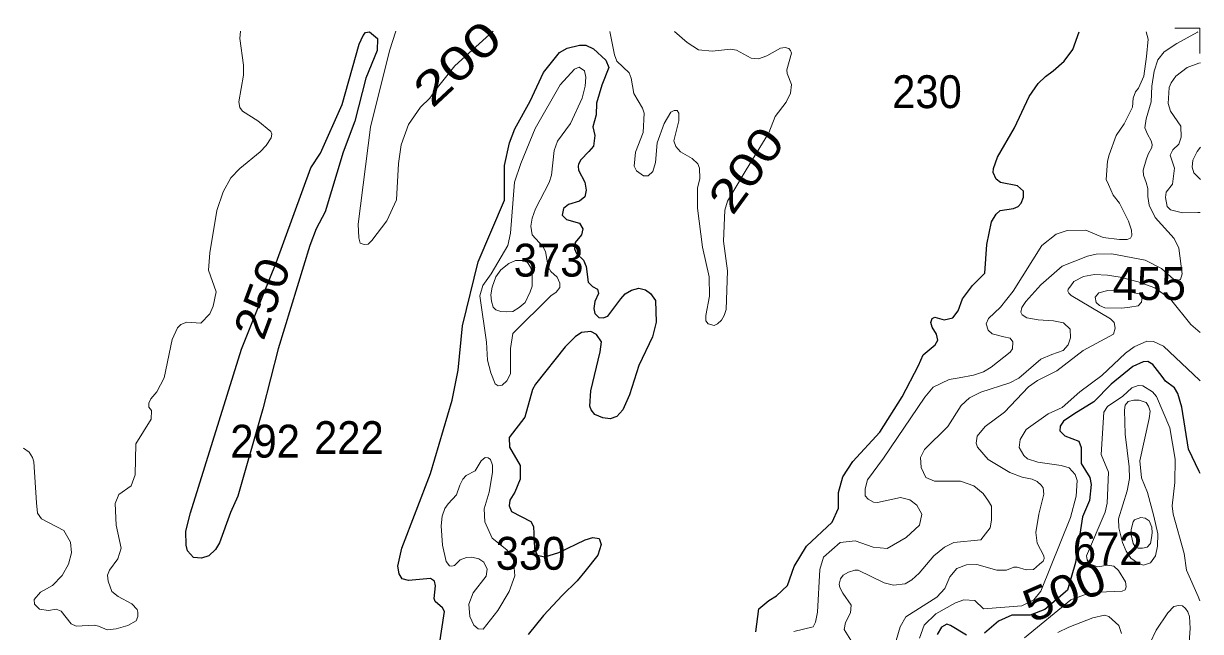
# Model space of a CAD drawing. Extents: x 499.9 to 555.3, y 9281.5 to 9336.8.
# Drawn here: x 549.61 to 555.34, y 9333.84 to 9336.8 of the extents above; entities that cross this region are included whole.
import ezdxf
from ezdxf.enums import TextEntityAlignment as Align

# ---------------------------------------------------------------- set-up
doc = ezdxf.new("R2010")
doc.units = 0
doc.header["$LTSCALE"] = 0.064
for name, color, linetype, lineweight in [('1', 7, 'Continuous', 25), ('2', 7, 'Continuous', 13), ('63', 7, 'Continuous', 13)]:
    doc.layers.add(name, color=color, linetype=linetype, lineweight=lineweight)
doc.layers.add('21', color=7, linetype='Continuous')
doc.layers.add('61', color=7, linetype='Continuous')

msp = doc.modelspace()

# ---------------------------------------------------------------- linework, layer by layer
at = {"layer": '1'}
msp.add_lwpolyline([(550.4187, 9334.4223), (550.6665, 9335.2176), (550.7746, 9335.4868), (550.8353, 9335.6382), (551.0048, 9336.1013), (551.0522, 9336.1729), (551.1571, 9336.4093), (551.2399, 9336.7025), (551.2589, 9336.7457), (551.2711, 9336.7591), (551.2901, 9336.7636), (551.3297, 9336.7309), (551.3282, 9336.6715), (551.2731, 9336.5372), (551.2185, 9336.3289), (551.1616, 9336.1779), (551.0748, 9335.8875), (551.0312, 9335.8041), (550.9998, 9335.7224), (550.8455, 9335.2205), (550.7715, 9334.928), (550.649, 9334.5029), (550.6129, 9334.4235), (550.5599, 9334.2763), (550.5396, 9334.2439), (550.5082, 9334.2127), (550.4722, 9334.2007), (550.433, 9334.2051), (550.4041, 9334.2372), (550.3978, 9334.2644), (550.3962, 9334.3327)], close=True, dxfattribs=at)
for points in [[(553.1716, 9333.8418), (553.1865, 9333.9546), (553.2346, 9333.9949), (553.2721, 9334.017), (553.3255, 9334.0688), (553.3578, 9334.1608), (553.4181, 9334.2595), (553.5429, 9334.3758), (553.5742, 9334.445), (553.5746, 9334.5213), (553.5964, 9334.5966), (553.6446, 9334.6709), (553.7755, 9334.8149), (553.8848, 9334.9861), (553.9645, 9335.1389), (553.9876, 9335.1907), (554.0164, 9335.2146), (554.045, 9335.2397), (554.0581, 9335.2624), (554.0513, 9335.2909), (554.0301, 9335.3252), (554.0246, 9335.3485), (554.0304, 9335.3675), (554.0438, 9335.3748), (554.0892, 9335.3604), (554.1319, 9335.3705), (554.1569, 9335.4047), (554.1778, 9335.4635), (554.2271, 9335.5288), (554.2871, 9335.5879), (554.2972, 9335.7286), (554.3192, 9335.8383), (554.3419, 9335.8757), (554.3617, 9335.8933), (554.4272, 9335.9024), (554.4496, 9335.9128), (554.4646, 9335.9291), (554.4753, 9335.9586), (554.4749, 9335.9869), (554.4463, 9336.013), (554.3642, 9336.0289), (554.3419, 9336.0453), (554.3282, 9336.0777), (554.3287, 9336.0973), (554.3493, 9336.1535), (554.4316, 9336.2964), (554.5028, 9336.4478), (554.5462, 9336.5116), (554.5821, 9336.5458), (554.6194, 9336.5723), (554.6731, 9336.6198), (554.716, 9336.6772), (554.7464, 9336.7634)], [(551.6297, 9333.771), (551.6563, 9333.9413), (551.6461, 9333.9597), (551.6103, 9333.9906), (551.6045, 9334.0042), (551.6119, 9334.0662), (551.607, 9334.0898), (551.5866, 9334.1027), (551.4809, 9334.0919), (551.4494, 9334.1004), (551.4346, 9334.1248), (551.428, 9334.1623), (551.4473, 9334.2497), (551.5866, 9334.6137), (551.693, 9334.9694), (551.7218, 9335.1158), (551.744, 9335.3322), (551.8194, 9335.6441), (551.9474, 9335.9433), (551.948, 9336.1129), (551.9727, 9336.2223), (551.9973, 9336.2912), (552.0724, 9336.4256), (552.1385, 9336.5655), (552.2154, 9336.6619), (552.2535, 9336.6841), (552.3132, 9336.6984), (552.3442, 9336.6984), (552.3808, 9336.6794), (552.4408, 9336.6254), (552.4555, 9336.5886), (552.4212, 9336.5029), (552.3954, 9336.4162), (552.3946, 9336.3588), (552.3779, 9336.3011), (552.3883, 9336.2586), (552.3816, 9336.2062), (552.3587, 9336.1806), (552.319, 9336.1398), (552.309, 9336.1193), (552.3068, 9336.1086), (552.3087, 9336.0888), (552.3397, 9336.0316), (552.3456, 9335.9928), (552.3385, 9335.96), (552.3138, 9335.938)], [(552.3138, 9335.938), (552.2598, 9335.9228), (552.2345, 9335.9027), (552.2287, 9335.8703), (552.249, 9335.8498), (552.3127, 9335.832)], [(552.3127, 9335.832), (552.3295, 9335.804), (552.322, 9335.7742), (552.2917, 9335.7376), (552.2885, 9335.7072), (552.2986, 9335.684), (552.3323, 9335.6512), (552.345, 9335.6205), (552.356, 9335.5442), (552.3764, 9335.5236), (552.4009, 9335.5111), (552.405, 9335.4899), (552.3874, 9335.45), (552.3825, 9335.4167), (552.3876, 9335.3917), (552.407, 9335.3717), (552.4281, 9335.3702), (552.4504, 9335.379), (552.5138, 9335.4633), (552.5347, 9335.4876), (552.5659, 9335.5061), (552.6028, 9335.5154), (552.6343, 9335.5079), (552.6585, 9335.4893), (552.6827, 9335.4546), (552.6863, 9335.349), (552.6684, 9335.2782), (552.6021, 9335.1389), (552.5561, 9334.9964), (552.5235, 9334.9229), (552.4945, 9334.8907), (552.4632, 9334.8799), (552.4267, 9334.8846), (552.3879, 9334.9), (552.3692, 9334.9224), (552.3636, 9334.9415), (552.3682, 9335.0156), (552.4142, 9335.2059), (552.4204, 9335.2543), (552.3966, 9335.2898), (552.3679, 9335.3051), (552.3228, 9335.2996), (552.2912, 9335.2783), (552.2438, 9335.2296), (552.0981, 9335.0472), (552.0846, 9335.0219), (552.0464, 9334.8875), (551.9705, 9334.7886), (551.9717, 9334.741), (552.0243, 9334.6529), (552.0241, 9334.5851), (551.9974, 9334.5229), (551.9738, 9334.483), (551.9709, 9334.4554), (551.982, 9334.428), (552.0766, 9334.3789), (552.0893, 9334.3557), (552.0945, 9334.2477), (552.1073, 9334.2161), (552.1446, 9334.208), (552.2132, 9334.2279), (552.3403, 9334.2905), (552.3777, 9334.3013), (552.4084, 9334.2965), (552.4186, 9334.2675), (552.4024, 9334.2152), (552.3395, 9334.136), (552.3019, 9334.091), (552.2281, 9334.0202), (552.1377, 9333.9222), (552.0628, 9333.8302)], [(555.3356, 9334.6129), (555.331, 9334.6227), (555.2797, 9334.7317), (555.2467, 9334.9367), (555.2272, 9335.0019), (555.211, 9335.0295), (555.1674, 9335.0623), (555.151, 9335.0848), (555.1048, 9335.1441), (555.0811, 9335.1578), (555.0582, 9335.1571), (555.0078, 9335.1341), (554.9031, 9335.0484), (554.8181, 9334.9623), (554.7211, 9334.9022), (554.6696, 9334.8673), (554.6536, 9334.8433), (554.6525, 9334.8208), (554.6761, 9334.7973), (554.7446, 9334.7705), (554.7564, 9334.7405), (554.7563, 9334.6619), (554.7981, 9334.5945), (554.8058, 9334.5594), (554.7965, 9334.4815), (554.7621, 9334.4018), (554.7295, 9334.1793), (554.6897, 9334.0454), (554.5793, 9333.9513), (554.5086, 9333.9233), (554.4191, 9333.9241), (554.3535, 9333.8949), (554.2849, 9333.8357)], [(554.1978, 9333.8268), (554.1207, 9333.8737), (554.1029, 9333.8795), (554.0767, 9333.8658), (554.0547, 9333.8301)]]:
    msp.add_lwpolyline(points, dxfattribs=at)
at = {"layer": '2'}
for points in [[(549.6928, 9334.3932), (549.8023, 9334.3365), (549.8341, 9334.2794), (549.8388, 9334.2273), (549.8246, 9334.1713), (549.7928, 9334.1172), (549.7458, 9334.0684), (549.6883, 9334.0358), (549.6568, 9333.9998), (549.6584, 9333.9765), (549.6838, 9333.9533), (549.7261, 9333.9471), (549.765, 9333.9529), (549.7891, 9333.9437), (549.838, 9333.8817), (549.861, 9333.8694), (549.9515, 9333.8755), (549.9704, 9333.8703), (550.0131, 9333.8531), (550.0562, 9333.8569), (550.1126, 9333.874), (550.1534, 9333.8969), (550.1625, 9333.917), (550.1614, 9333.9381), (550.1583, 9333.9505), (550.1334, 9333.9785), (550.066, 9334.0148), (550.0354, 9334.0384), (550.0172, 9334.0891), (550.0136, 9334.1181), (550.0243, 9334.1432), (550.0653, 9334.1975), (550.0807, 9334.2501), (550.0569, 9334.361), (550.051, 9334.4672), (550.0701, 9334.5115), (550.1303, 9334.5525), (550.1483, 9334.607), (550.153, 9334.7576), (550.2269, 9334.8772), (550.2287, 9334.9191), (550.2162, 9334.9366), (550.2151, 9334.9549), (550.2248, 9334.9771), (550.2543, 9335.01), (550.2895, 9335.0792), (550.3294, 9335.2662), (550.355, 9335.3223), (550.3722, 9335.3392), (550.4003, 9335.3501), (550.4687, 9335.3452), (550.5125, 9335.3896), (550.5282, 9335.427), (550.544, 9335.4978), (550.5063, 9335.6029), (550.5124, 9335.6872), (550.5472, 9335.8926), (550.5783, 9335.9841), (550.6149, 9336.0515), (550.6593, 9336.0975), (550.7574, 9336.1782), (550.7876, 9336.2101), (550.8114, 9336.2474), (550.8138, 9336.2655), (550.8091, 9336.278), (550.7469, 9336.3304), (550.6713, 9336.3761), (550.6587, 9336.3948), (550.6539, 9336.4223), (550.6762, 9336.5522), (550.6759, 9336.6001), (550.6588, 9336.7304), (550.6627, 9336.7669)], [(551.4193, 9336.7663), (551.3879, 9336.67), (551.2955, 9336.2983), (551.2349, 9335.8272), (551.2376, 9335.761), (551.2446, 9335.7351), (551.2651, 9335.7279), (551.2841, 9335.7297), (551.3024, 9335.7472), (551.3744, 9335.8433), (551.4212, 9335.945), (551.4323, 9336.1225), (551.4447, 9336.213), (551.4795, 9336.312), (551.5393, 9336.3958), (551.5837, 9336.4396), (551.6217, 9336.4927), (551.7057, 9336.598), (551.8931, 9336.7659)], [(552.4608, 9336.7653), (552.4837, 9336.6509), (552.495, 9336.6204), (552.5544, 9336.5628), (552.5645, 9336.5368), (552.5783, 9336.4631), (552.6203, 9336.3912), (552.6288, 9336.3676), (552.6228, 9336.2729), (552.5865, 9336.1774), (552.5785, 9336.1092), (552.5899, 9336.0859), (552.6243, 9336.0621), (552.6481, 9336.0625), (552.671, 9336.0833), (552.6832, 9336.1264), (552.6915, 9336.2219), (552.7248, 9336.3172), (552.7585, 9336.372), (552.7736, 9336.3793), (552.7881, 9336.3798), (552.797, 9336.3664), (552.7976, 9336.3294), (552.7732, 9336.2323), (552.7824, 9336.2049), (552.8056, 9336.1785), (552.8626, 9336.1467), (552.8895, 9336.1198), (552.8972, 9336.0994), (552.8995, 9336.0492), (552.887, 9336.0015), (552.887, 9335.9053), (552.9125, 9335.7143), (552.9443, 9335.57), (552.9458, 9335.4771), (552.9287, 9335.3818), (552.9284, 9335.3569), (552.9397, 9335.3413), (552.9689, 9335.3335), (552.9858, 9335.341), (553.0044, 9335.3588), (553.0182, 9335.3818), (553.0269, 9335.4113), (553.0333, 9335.6004), (553.0143, 9335.7437), (553.0201, 9335.8955), (553.0332, 9335.9383), (553.1251, 9336.0909), (553.2352, 9336.2709), (553.2656, 9336.3513), (553.3198, 9336.4202), (553.3407, 9336.464), (553.345, 9336.5067), (553.3248, 9336.5604), (553.323, 9336.5772), (553.3453, 9336.6591), (553.3407, 9336.6718), (553.333, 9336.681), (553.3146, 9336.687), (553.2913, 9336.684), (553.2259, 9336.6462), (553.1841, 9336.6319), (553.1488, 9336.6345), (553.0779, 9336.6744), (553.0504, 9336.6786), (552.9593, 9336.6684), (552.8931, 9336.6761), (552.8369, 9336.7102), (552.7755, 9336.7651)], [(554.3193, 9334.4538), (554.3044, 9334.4791), (554.2783, 9334.516), (554.233, 9334.553), (554.169, 9334.5754), (554.0425, 9334.5757), (554.0003, 9334.5944), (553.9773, 9334.6424), (553.9744, 9334.6907), (553.9932, 9334.7297), (554.1072, 9334.8414), (554.1725, 9334.944), (554.2128, 9334.9812), (554.2685, 9335.0083), (554.4085, 9335.0538), (554.452, 9335.0774), (554.5603, 9335.1694), (554.613, 9335.1924), (554.6688, 9335.212), (554.6929, 9335.239), (554.7049, 9335.2736), (554.7034, 9335.3157), (554.6703, 9335.3472), (554.6222, 9335.3563), (554.547, 9335.3608), (554.4914, 9335.3713), (554.4684, 9335.3856), (554.4618, 9335.3978), (554.4666, 9335.4215), (554.487, 9335.4498), (554.5607, 9335.5315), (554.6632, 9335.6226), (554.7865, 9335.6718), (554.8287, 9335.68), (554.905, 9335.6816), (555.0673, 9335.6512), (555.1469, 9335.6115), (555.208, 9335.5573), (555.2201, 9335.5531), (555.2395, 9335.5581), (555.2487, 9335.5853), (555.2324, 9335.7093), (555.2094, 9335.7562), (555.1173, 9335.859), (555.0878, 9335.92), (555.0803, 9335.9621), (555.0803, 9336.0011), (555.0727, 9336.0297), (555.0592, 9336.0658), (555.0577, 9336.0898), (555.0727, 9336.1394), (555.0833, 9336.168), (555.1001, 9336.1995), (555.1021, 9336.2146), (555.0968, 9336.2326), (555.08, 9336.265), (555.0659, 9336.2952), (555.0727, 9336.3393), (555.0968, 9336.422), (555.1005, 9336.4984), (555.1118, 9336.5708), (555.1299, 9336.6264), (555.1614, 9336.6655), (555.2216, 9336.7061), (555.3224, 9336.7617), (555.3244, 9336.7628)], [(555.0205, 9336.471), (555.0361, 9336.4882), (555.0611, 9336.5477), (555.0742, 9336.6431), (555.083, 9336.7275), (555.0736, 9336.7631)], [(555.3367, 9335.884), (555.325, 9335.8837), (555.2497, 9335.8818), (555.1922, 9335.8964), (555.1755, 9335.9131), (555.1664, 9335.9561), (555.1704, 9335.9822), (555.2019, 9336.0211), (555.2107, 9336.0994), (555.1902, 9336.1622), (555.2033, 9336.1882), (555.2324, 9336.216), (555.2439, 9336.2506), (555.2423, 9336.3033), (555.1914, 9336.3765), (555.1793, 9336.4136), (555.1854, 9336.4924), (555.195, 9336.5154), (555.2177, 9336.5476), (555.2727, 9336.5886), (555.3299, 9336.6099), (555.3374, 9336.6127)], [(553.3575, 9333.8444), (553.4506, 9333.8664), (553.4629, 9333.8895), (553.4726, 9333.9388), (553.4839, 9334.1457), (553.5016, 9334.2061), (553.582, 9334.2774), (553.6554, 9334.2856), (553.744, 9334.2554), (553.8122, 9334.248), (553.9038, 9334.3012), (553.969, 9334.3611), (553.9799, 9334.4154), (553.9563, 9334.4591), (553.9225, 9334.4856), (553.8767, 9334.4957), (553.7646, 9334.4727), (553.7442, 9334.4736), (553.7183, 9334.4876), (553.705, 9334.5037), (553.7051, 9334.5389), (553.715, 9334.5825), (553.793, 9334.6875), (553.9942, 9334.9854), (554.0357, 9335.0334), (554.1133, 9335.0701), (554.1616, 9335.0788), (554.2312, 9335.0914), (554.2804, 9335.1084), (554.3177, 9335.131), (554.4112, 9335.2038), (554.4215, 9335.2204), (554.424, 9335.2547), (554.4108, 9335.272), (554.379, 9335.279), (554.3227, 9335.2924), (554.3042, 9335.3101), (554.2937, 9335.3413), (554.3044, 9335.3676), (554.3628, 9335.4227), (554.4248, 9335.5001), (554.5656, 9335.7224), (554.6341, 9335.7777), (554.6879, 9335.796), (554.7784, 9335.7974), (554.8638, 9335.7622), (554.9432, 9335.7517), (554.9809, 9335.7525), (554.9974, 9335.7588), (555.0027, 9335.7716), (555.0021, 9335.7972), (554.987, 9335.8409), (554.9432, 9335.9283), (554.9121, 9335.9674), (554.8888, 9336.0198), (554.8783, 9336.0439), (554.884, 9336.1329), (554.8924, 9336.1646), (554.9271, 9336.2586), (554.9652, 9336.3151), (555.0064, 9336.3955), (555.0103, 9336.4408), (555.0205, 9336.471)], [(555.3369, 9336.0446), (555.3295, 9336.052), (555.3054, 9336.0761), (555.2964, 9336.1047), (555.3009, 9336.1377), (555.322, 9336.1798), (555.337, 9336.2017)], [(554.9227, 9335.3201), (554.9175, 9335.3474), (554.8999, 9335.3653), (554.7078, 9335.4799), (554.6969, 9335.4903), (554.6911, 9335.5009), (554.6935, 9335.5096), (554.7059, 9335.5271), (554.7211, 9335.5483), (554.7684, 9335.5719), (554.822, 9335.5814), (554.8851, 9335.579), (554.9466, 9335.568), (555.0342, 9335.5467), (555.1155, 9335.5161), (555.191, 9335.4623), (555.291, 9335.3387), (555.3362, 9335.3001)], [(554.4998, 9335.0343), (554.5439, 9335.0666), (554.6376, 9335.1135), (554.7657, 9335.2125), (554.914, 9335.2909), (554.9227, 9335.3201)], [(555.336, 9335.0647), (555.3332, 9335.0673), (555.1571, 9335.2323), (555.1087, 9335.2564), (555.0764, 9335.2579), (555.0149, 9335.2296), (554.9728, 9335.1988), (554.8578, 9335.0901), (554.7493, 9335.0103), (554.6637, 9334.9343), (554.5953, 9334.9037), (554.4878, 9334.828), (554.4589, 9334.7782), (554.454, 9334.7394), (554.4774, 9334.7008), (554.4951, 9334.6853), (554.5454, 9334.6678), (554.6582, 9334.6521), (554.6973, 9334.6408), (554.7271, 9334.6082), (554.7361, 9334.5785), (554.7328, 9334.5033), (554.7043, 9334.3997), (554.5598, 9334.0405), (554.5258, 9333.9976), (554.4678, 9333.969), (554.2813, 9333.9549), (554.239, 9333.9945), (554.1857, 9333.9976), (554.1446, 9333.9836), (554.0488, 9333.9308), (553.9921, 9333.8742), (553.9692, 9333.8122)], [(553.8437, 9333.7611), (553.8746, 9333.8661), (553.902, 9333.9149), (554.0534, 9334.0105), (554.0916, 9334.0535), (554.1174, 9334.1107), (554.1508, 9334.1503), (554.1985, 9334.1694), (554.2485, 9334.1696), (554.3456, 9334.1426), (554.3924, 9334.1428), (554.4278, 9334.157), (554.4446, 9334.1567), (554.488, 9334.1443), (554.5244, 9334.1457), (554.5537, 9334.1712), (554.5718, 9334.1869), (554.5754, 9334.1991), (554.5738, 9334.2118), (554.5428, 9334.2746), (554.5359, 9334.3259), (554.5494, 9334.416), (554.5751, 9334.5132), (554.572, 9334.5433), (554.5618, 9334.5568), (554.5427, 9334.5743), (554.5174, 9334.5861), (554.469, 9334.5946), (554.4085, 9334.6185), (554.3035, 9334.6806), (554.2516, 9334.7412), (554.2449, 9334.7601), (554.2498, 9334.7955), (554.2887, 9334.8422), (554.3829, 9334.9111), (554.4998, 9335.0343)], [(555.335, 9333.9939), (555.3255, 9334.0152), (555.2688, 9334.142), (555.2584, 9334.2246), (555.2044, 9334.4156), (555.1996, 9334.4563), (555.2121, 9334.5691), (555.2137, 9334.683), (555.1885, 9334.8358), (555.124, 9334.9877), (555.1039, 9335.0111), (555.0562, 9335.04), (555.0348, 9335.0415), (555.0032, 9335.03), (554.9594, 9334.9896), (554.885, 9334.9388), (554.8671, 9334.9118), (554.8544, 9334.7061), (554.889, 9334.6192), (554.8827, 9334.468), (554.8731, 9334.4258), (554.7831, 9334.2124), (554.7851, 9334.1923), (554.8008, 9334.1724), (554.8379, 9334.1585), (554.8839, 9334.1671), (554.9161, 9334.1622), (554.9383, 9334.141), (554.9717, 9334.0859), (554.9754, 9334.0613), (554.9707, 9334.0466), (554.9568, 9334.0401), (554.8416, 9334.0357), (554.8132, 9334.0303), (554.7725, 9334.0233), (554.7064, 9333.9986), (554.4807, 9333.8126)], [(549.605, 9334.7358), (549.6322, 9334.7175)], [(549.6322, 9334.7175), (549.6482, 9334.691), (549.6561, 9334.6707), (549.6679, 9334.4707), (549.6739, 9334.4194), (549.6928, 9334.3932)], [(554.0902, 9334.2554), (554.1355, 9334.2779), (554.2676, 9334.2907), (554.3127, 9334.3482), (554.3194, 9334.3864), (554.3193, 9334.4538)], [(553.6345, 9333.8027), (553.6019, 9333.8537), (553.6094, 9333.8872), (553.6329, 9333.9349), (553.6363, 9333.973), (553.5958, 9334.0305), (553.5811, 9334.0588), (553.5784, 9334.0744), (553.5841, 9334.1005), (553.598, 9334.118), (553.6231, 9334.1337), (553.6533, 9334.1421), (553.6709, 9334.1424), (553.7976, 9334.0812), (553.842, 9334.0695), (553.8984, 9334.0767), (553.9309, 9334.0949), (553.967, 9334.1277), (554.0387, 9334.212), (554.0902, 9334.2554)], [(554.9526, 9333.8338), (554.9401, 9333.8727), (554.8904, 9333.9179), (554.8694, 9333.9229), (554.8137, 9333.9106), (554.6956, 9333.8659), (554.6424, 9333.8386)], [(555.2774, 9333.7254), (555.287, 9333.8594), (555.2834, 9333.9172), (555.2751, 9333.9391), (555.2644, 9333.9561), (555.25, 9333.9687), (555.2297, 9333.9712), (555.207, 9333.9659), (555.1783, 9333.9351), (555.1223, 9333.8512), (555.0913, 9333.786)]]:
    msp.add_lwpolyline(points, dxfattribs=at)
for points in [[(552.0269, 9336.1216), (551.997, 9336.0313), (551.9777, 9335.7822), (551.9638, 9335.7227), (551.8832, 9335.5851), (551.8427, 9335.5279), (551.8274, 9335.4776), (551.8603, 9335.2528), (551.8644, 9335.165), (551.8805, 9335.1024), (551.9021, 9335.0495), (551.9168, 9335.0404), (551.9357, 9335.0425), (551.9585, 9335.0637), (551.9763, 9335.0975), (551.977, 9335.2215), (551.9879, 9335.294), (552.173, 9335.4786), (552.1988, 9335.4957), (552.2174, 9335.519), (552.218, 9335.5395), (552.2041, 9335.5683), (552.1741, 9335.596), (552.1597, 9335.6188), (552.147, 9335.6936), (552.1344, 9335.7186), (552.0821, 9335.7751), (552.0757, 9335.817), (552.0819, 9335.8559), (552.0983, 9335.9013), (552.166, 9336.0293), (552.1769, 9336.0652), (552.1893, 9336.186), (552.2054, 9336.23), (552.2698, 9336.3174), (552.326, 9336.4396), (552.341, 9336.4981), (552.344, 9336.5426), (552.3369, 9336.5731), (552.3107, 9336.5914), (552.2891, 9336.5815), (552.219, 9336.505), (552.0968, 9336.2929)], [(552.0482, 9335.4456), (552.0721, 9335.4967), (552.0833, 9335.5254), (552.0833, 9335.5558), (552.0833, 9335.5909), (552.0737, 9335.618), (552.0594, 9335.6404), (552.037, 9335.65), (552.0019, 9335.65), (551.9684, 9335.6356), (551.93, 9335.6053), (551.9061, 9335.5701), (551.8885, 9335.5206), (551.8805, 9335.4823), (551.8837, 9335.452), (551.8933, 9335.4232), (551.9061, 9335.4105), (551.93, 9335.4009), (551.9588, 9335.3993), (551.9891, 9335.4009), (552.0195, 9335.4216)], [(554.9548, 9335.4181), (554.8722, 9335.4198), (554.8457, 9335.4307), (554.8302, 9335.445), (554.8253, 9335.4707), (554.8423, 9335.492), (554.8859, 9335.5039), (554.9455, 9335.5051), (555.0397, 9335.4882), (555.0529, 9335.4735), (555.0498, 9335.4479), (555.0333, 9335.4299), (554.9942, 9335.4223)], [(554.9382, 9334.3922), (554.94, 9334.348), (554.9574, 9334.2776), (554.9757, 9334.2345), (554.9983, 9334.2015), (555.0305, 9334.1786), (555.0606, 9334.1673), (555.0945, 9334.1792), (555.1182, 9334.212), (555.1288, 9334.2593), (555.1304, 9334.3201), (555.1108, 9334.4057), (555.0796, 9334.5212), (555.0499, 9334.5926), (555.0422, 9334.6748), (555.0875, 9334.8809), (555.0928, 9334.9163), (555.0847, 9334.9407), (555.0734, 9334.9587), (555.0387, 9334.9701), (555.013, 9334.9704), (554.9846, 9334.963), (554.9707, 9334.9458), (554.9671, 9334.9213), (554.9703, 9334.8039), (554.9909, 9334.6455), (554.9925, 9334.589), (554.9809, 9334.5294)], [(551.7884, 9334.2067), (551.8223, 9334.1979), (551.8464, 9334.1824), (551.8641, 9334.1477), (551.8578, 9334.1133), (551.7956, 9334.0317), (551.7748, 9333.9778), (551.7797, 9333.9175), (551.7983, 9333.8743), (551.8199, 9333.8573), (551.8438, 9333.8557), (551.9151, 9333.9472), (551.9707, 9334.0384), (551.9974, 9334.115), (551.9919, 9334.1933), (551.9584, 9334.2411), (551.888, 9334.2981), (551.8526, 9334.3782), (551.8494, 9334.4419), (551.8733, 9334.5221), (551.8888, 9334.6181), (551.8886, 9334.6539), (551.8795, 9334.6807), (551.8687, 9334.6895), (551.854, 9334.691), (551.8335, 9334.6756), (551.8044, 9334.6266), (551.7607, 9334.604), (551.7446, 9334.5853), (551.73, 9334.5564), (551.7137, 9334.5087), (551.6727, 9334.4655), (551.6568, 9334.4426), (551.6438, 9334.4049), (551.6392, 9334.3583), (551.6455, 9334.2643), (551.6642, 9334.185), (551.6802, 9334.1641), (551.6907, 9334.1617), (551.7044, 9334.1648), (551.7323, 9334.1936), (551.763, 9334.204)], [(555.0545, 9334.2492), (555.0783, 9334.2548), (555.0933, 9334.273), (555.0996, 9334.2993), (555.1021, 9334.3244), (555.1008, 9334.3519), (555.0871, 9334.3833), (555.0683, 9334.3958), (555.047, 9334.3983), (555.0169, 9334.3883), (555.0094, 9334.3776), (554.9993, 9334.3407), (555.0006, 9334.3143), (555.0094, 9334.2717), (555.0206, 9334.2554), (555.0332, 9334.2492)]]:
    msp.add_lwpolyline(points, close=True, dxfattribs=at)
at = {"layer": '63'}
msp.add_lwpolyline([(555.3341, 9336.6575), (555.3341, 9336.7807), (555.2127, 9336.7807)], dxfattribs=at)

# ---------------------------------------------------------------- texts
at = {"layer": '21', "width": 0.95}
for s, p in [('230', (553.8359, 9336.3915)), ('373', (551.9932, 9335.5716)), ('292', (550.6123, 9334.6906)), ('222', (551.0203, 9334.7078)), ('330', (551.9052, 9334.1447))]:
    msp.add_text(s, height=0.16, dxfattribs=at).set_placement(p)
at = {"layer": '21'}
msp.add_text('455', height=0.16, dxfattribs=at).set_placement((554.9095, 9335.4579))
at = {"layer": '21', "width": 0.95}
msp.add_text('672', height=0.16, dxfattribs=at).set_placement((555.0551, 9334.1674), align=Align.RIGHT)
at = {"layer": '61'}
for s, rotation, width, p in [('200', 42.955, 1.35, (551.7722, 9336.5506)), ('200', 53.943, 1.25, (553.1897, 9336.0438)), ('250', 69.643, 1.1, (550.842, 9335.4387)), ('500', 23.334, 1.15, (554.706, 9333.9653))]:
    msp.add_text(s, height=0.16, rotation=rotation, dxfattribs=dict(at, width=width)).set_placement(p, align=Align.CENTER)

doc.saveas('drawing.dxf')
